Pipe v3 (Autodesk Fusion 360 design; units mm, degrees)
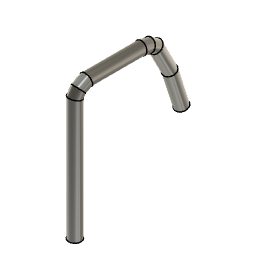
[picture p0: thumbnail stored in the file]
sketch "Sketch1" plane through (0, 0, 0) normal (1, 0, 0) x axis (0, 1, 0)
  curve K1 (130, 100) -> (0, 0)
sketch "Sketch2" plane through (0, 0, 0) normal (1, 0, 0) x axis (0, 1, 0)
sketch "Sketch3" plane through (0, 0, 0) normal (1, 0, 0) x axis (0, 1, 0)
  line L1 (0, 100) -> (0, 0)
  line L2 (2.9083, 104.4384) -> (0, 100)
  line L3 (9.5215, 107.8674) -> (2.9083, 104.4384)
  line L4 (15, 107.8674) -> (9.5215, 107.8674)
  line L5 (23.7275, 107.8674) -> (15, 107.8674)
  line L6 (35, 107.8674) -> (23.7275, 107.8674)
  line L7 (53.8541, 107.8674) -> (35, 107.8674)
  line L8 (60.4247, 106.6341) -> (53.8541, 107.8674)
  line L9 (65.7711, 103.2215) -> (60.4247, 106.6341)
  line L10 (70, 95) -> (65.7711, 103.2215)
  line L11 (73.8276, 87.5586) -> (70, 95)
  line L12 (77.4486, 80.5189) -> (73.8276, 87.5586)
  line L13 (83.6305, 61.3601) -> (77.4486, 80.5189)
  line L14 (85.608, 55.2315) -> (83.6305, 61.3601)
  line L15 (87.119, 50.5486) -> (85.608, 55.2315)
  point P1 (0, 0)
  point P2 (0, 0)
  coincident P1 P2
  vertical L1
  perpendicular L1 L4
  parallel L4 L5
  parallel L5 L6
  parallel L6 L7
  parallel L10 L11
  parallel L10 L12
  parallel L13 L14
  parallel L14 L15
pipe "Pipe2" SectionSize 10 SectionThickness 2.5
